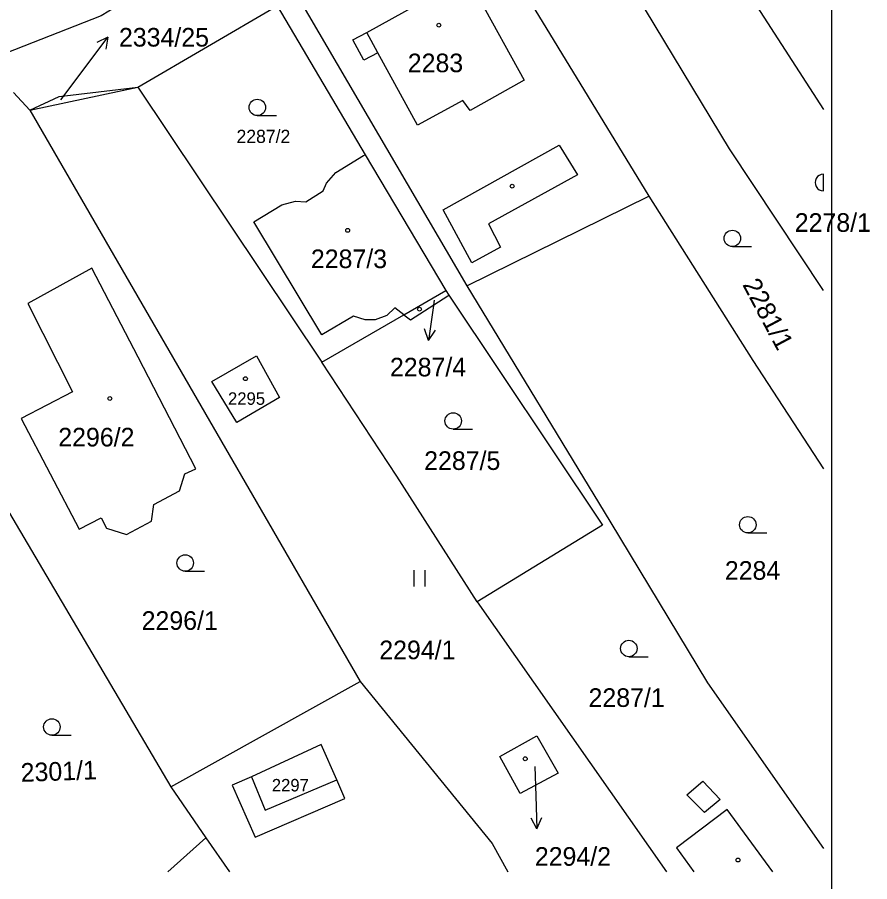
# Model space of a CAD drawing. Extents: x -606208 to -605570, y -1157873 to -1157573.
# Drawn here: x -605647.7 to -605569.8, y -1157765.4 to -1157686.5 of the extents above; entities that cross this region are included whole.
import ezdxf

# ---------------------------------------------------------------- set-up
doc = ezdxf.new("R2010")
doc.units = 0
doc.layers.add('Vrstva 1', color=7, linetype='Continuous')
doc.layers.add('Vrstva 62', color=7, linetype='Continuous')

msp = doc.modelspace()

# ---------------------------------------------------------------- linework, layer by layer
at = {"layer": 'Vrstva 1'}
msp.add_lwpolyline([(-606203.28, -1157873.46), (-605573.29, -1157873.46), (-605573.29, -1157576.47), (-606203.28, -1157576.47)], close=True, dxfattribs=at)
at = {"layer": 'Vrstva 62'}
for p, q in [((-605606.49, -1157675.87), (-605590.01, -1157702.84)), ((-605615.75, -1157687.9), (-605608.3, -1157683.78)), ((-605622.17, -1157684.45), (-605606.61, -1157711.04)), ((-605605.59, -1157684.64), (-605601.39, -1157692.27)), ((-605636.65, -1157692.89), (-605623.94, -1157685.48)), ((-605623.94, -1157685.48), (-605615.89, -1157699.06)), ((-605617.02, -1157688.58), (-605615.75, -1157687.9)), ((-605614.74, -1157689.77), (-605615.75, -1157687.9)), ((-605641.18, -1157690.74), (-605639.374, -1157688.343)), ((-605639.374, -1157688.343), (-605640.377, -1157688.842)), ((-605639.374, -1157688.343), (-605639.577, -1157689.444)), ((-605616.01, -1157690.44), (-605617.02, -1157688.58)), ((-605614.74, -1157689.77), (-605616.01, -1157690.44)), ((-605611.13, -1157696.38), (-605614.74, -1157689.77)), ((-605643.68, -1157694.07), (-605641.18, -1157690.74)), ((-605646.49, -1157694.99), (-605636.65, -1157692.89)), ((-605636.65, -1157692.89), (-605619.85, -1157717.98)), ((-605601.39, -1157692.27), (-605606.3, -1157695.04)), ((-605647.99, -1157693.4), (-605646.49, -1157694.99)), ((-605606.98, -1157694.11), (-605611.13, -1157696.38)), ((-605606.3, -1157695.04), (-605606.98, -1157694.11)), ((-605625.743, -1157695.5), (-605623.993, -1157695.5)), ((-605608.78, -1157704.09), (-605598.19, -1157698.2)), ((-605598.19, -1157698.2), (-605596.51, -1157700.91)), ((-605615.89, -1157699.06), (-605608.55, -1157711.45)), ((-605596.51, -1157700.91), (-605604.64, -1157705.37)), ((-605574.07, -1157702.35), (-605574.07, -1157700.85)), ((-605574.08, -1157702.35), (-605574.07, -1157702.35)), ((-605606.61, -1157711.04), (-605590.01, -1157702.84)), ((-605664.95, -1157703.71), (-605633.63, -1157756.72)), ((-605606.17, -1157708.92), (-605608.78, -1157704.09)), ((-605604.64, -1157705.37), (-605603.55, -1157707.49)), ((-605603.55, -1157707.49), (-605606.17, -1157708.92)), ((-605582.383, -1157707.45), (-605580.633, -1157707.45)), ((-605612.37, -1157713.66), (-605608.55, -1157711.45)), ((-605608.55, -1157711.45), (-605608.26, -1157711.88)), ((-605608.26, -1157711.88), (-605594.24, -1157732.86)), ((-605609.61, -1157712.34), (-605609.7, -1157713.03)), ((-605609.7, -1157713.03), (-605610.118, -1157716.002)), ((-605619.85, -1157717.98), (-605612.37, -1157713.66)), ((-605610.118, -1157716.002), (-605610.474, -1157714.94)), ((-605610.118, -1157716.002), (-605609.482, -1157715.08)), ((-605607.863, -1157724.1), (-605606.113, -1157724.1)), ((-605594.24, -1157732.86), (-605605.67, -1157739.85)), ((-605580.973, -1157733.57), (-605579.223, -1157733.57)), ((-605632.323, -1157737.06), (-605630.573, -1157737.06)), ((-605611.411, -1157738.45), (-605611.411, -1157736.95)), ((-605610.41, -1157738.45), (-605610.41, -1157736.95)), ((-605591.833, -1157744.86), (-605590.083, -1157744.86)), ((-605633.63, -1157756.72), (-605616.35, -1157747.13)), ((-605644.493, -1157752.02), (-605642.743, -1157752.02)), ((-605600.42, -1157754.87), (-605600.33, -1157757.56)), ((-605626.27, -1157755.82), (-605625.01, -1157758.87)), ((-605625.01, -1157758.87), (-605618.49, -1157756.1)), ((-605633.63, -1157756.72), (-605630.43, -1157761.39)), ((-605586.53, -1157757.47), (-605585.09, -1157756.21)), ((-605585.09, -1157756.21), (-605583.49, -1157757.9)), ((-605600.33, -1157757.56), (-605600.225, -1157760.559)), ((-605584.93, -1157759.08), (-605586.53, -1157757.47)), ((-605583.49, -1157757.9), (-605584.93, -1157759.08)), ((-605600.225, -1157760.559), (-605600.761, -1157759.576)), ((-605600.225, -1157760.559), (-605599.76, -1157759.541))]:
    msp.add_line(p, q, dxfattribs=at)
for points in [[(-605591.36, -1157668.19), (-605574.07, -1157694.95)], [(-605574.07, -1157711.46), (-605582.64, -1157698.54), (-605598.85, -1157671.69)], [(-605634.09, -1157680.59), (-605637.18, -1157684.66), (-605639.98, -1157686.4), (-605673.75, -1157699.63)], [(-605646.49, -1157694.99), (-605643.84, -1157693.74), (-605636.65, -1157692.89)], [(-605646.49, -1157694.99), (-605623.59, -1157734.59), (-605616.35, -1157747.13)], [(-605612.37, -1157713.66), (-605613.18, -1157713.04), (-605613.93, -1157713.72), (-605615, -1157714.13), (-605615.91, -1157714.13), (-605616.96, -1157713.78), (-605619.86, -1157715.51), (-605626.05, -1157705.19), (-605623.49, -1157703.65), (-605622.26, -1157703.3), (-605621.31, -1157703.35), (-605619.74, -1157702.35), (-605619.43, -1157701.67), (-605618.57, -1157700.68), (-605616.05, -1157699.15), (-605615.89, -1157699.06)], [(-605590.01, -1157702.84), (-605580.5, -1157717.84), (-605574.07, -1157727.72)], [(-605640.84, -1157709.4), (-605646.68, -1157712.64), (-605642.61, -1157720.69), (-605647.31, -1157723.13), (-605642.01, -1157733.23), (-605639.99, -1157732.2), (-605639.5, -1157733.14), (-605637.69, -1157733.7), (-605635.41, -1157732.48), (-605635.18, -1157730.96), (-605632.84, -1157729.72), (-605632.36, -1157728.19), (-605631.34, -1157727.72), (-605636.63, -1157717.54), (-605640.84, -1157709.4)], [(-605606.61, -1157711.04), (-605593.56, -1157732.48), (-605584.64, -1157747.24), (-605574.07, -1157762.36)], [(-605612.37, -1157713.66), (-605611.77, -1157714.12), (-605608.35, -1157711.95), (-605608.26, -1157711.88)], [(-605623.72, -1157721.22), (-605627.61, -1157723.49), (-605629.89, -1157719.76), (-605625.82, -1157717.4), (-605623.72, -1157721.22)], [(-605605.67, -1157739.85), (-605613, -1157728.38), (-605619.85, -1157717.98)], [(-605605.67, -1157739.85), (-605588.4, -1157764.47)], [(-605616.35, -1157747.13), (-605604.31, -1157761.9), (-605602.87, -1157764.47)], [(-605600.22, -1157752.09), (-605598.28, -1157755.49), (-605601.75, -1157757.34), (-605603.6, -1157753.95), (-605600.22, -1157752.09)], [(-605628.05, -1157756.57), (-605625.95, -1157761.32), (-605617.74, -1157757.79), (-605618.49, -1157756.1), (-605619.92, -1157752.88), (-605626.27, -1157755.82), (-605628.05, -1157756.57)], [(-605578.7, -1157764.47), (-605582.85, -1157758.79), (-605587.49, -1157762.28), (-605585.89, -1157764.47)], [(-605630.43, -1157761.39), (-605633.9, -1157764.47)], [(-605630.43, -1157761.39), (-605628.29, -1157764.47)]]:
    msp.add_lwpolyline(points, dxfattribs=at)
for centre, radius in [((-605609.177, -1157687.249), 0.175), ((-605625.743, -1157694.75), 0.75), ((-605602.477, -1157701.929), 0.175), ((-605617.497, -1157705.969), 0.175), ((-605582.383, -1157706.7), 0.75), ((-605610.937, -1157713.159), 0.175), ((-605626.827, -1157719.499), 0.175), ((-605639.207, -1157721.299), 0.175), ((-605607.863, -1157723.35), 0.75), ((-605580.973, -1157732.82), 0.75), ((-605632.323, -1157736.31), 0.75), ((-605591.833, -1157744.11), 0.75), ((-605644.493, -1157751.27), 0.75), ((-605601.287, -1157754.169), 0.175), ((-605581.867, -1157763.409), 0.175)]:
    msp.add_circle(centre, radius, dxfattribs=at)
msp.add_arc((-605574.083, -1157701.6), 0.75, 89.02621, 270.97379, dxfattribs=at)

# ---------------------------------------------------------------- texts
for s, height, p in [('2334/25', 1.7, (-605638.37, -1157689.2)), ('2283', 1.7, (-605612.01, -1157691.54)), ('2287/2', 1.2, (-605627.64, -1157697.99)), ('2278/1', 1.7, (-605576.688, -1157706.1)), ('2287/3', 1.7, (-605620.853, -1157709.41)), ('2287/4', 1.7, (-605613.636, -1157719.29)), ('2295', 1.139, (-605628.42, -1157721.88)), ('2296/2', 1.7, (-605643.91, -1157725.68)), ('2287/5', 1.7, (-605610.513, -1157727.82)), ('2284', 1.7, (-605583.07, -1157737.84)), ('2296/1', 1.7, (-605636.3, -1157742.41)), ('2294/1', 1.7, (-605614.61, -1157745.09)), ('2287/1', 1.7, (-605595.51, -1157749.44)), ('2297', 1.139, (-605624.42, -1157757.15)), ('2294/2', 1.7, (-605600.41, -1157763.93))]:
    msp.add_text(s, height=height, dxfattribs=at).set_placement(p)
for s, rotation, p in [('2281/1', 298, (-605581.5, -1157710.91)), ('2301/1', 2, (-605647.31, -1157756.28))]:
    msp.add_text(s, height=1.7, rotation=rotation, dxfattribs=at).set_placement(p)

doc.saveas('drawing.dxf')
